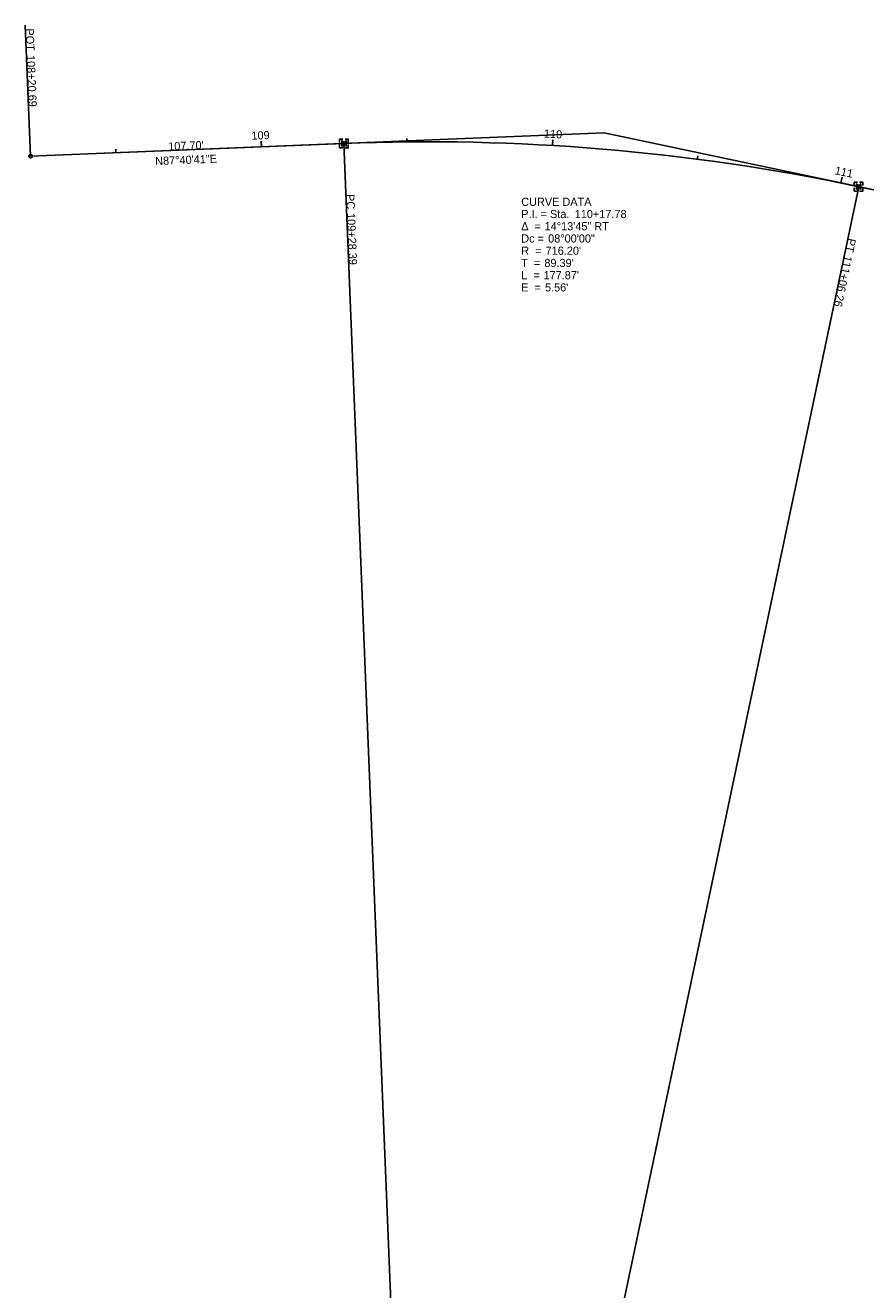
# Model space of a CAD drawing. Extents: x 2003596 to 2006933, y 570827 to 573780.
# Drawn here: x 2003595.8 to 2003884.4, y 572548.4 to 572982.7 of the extents above; entities that cross this region are included whole.
import ezdxf

# ---------------------------------------------------------------- set-up
doc = ezdxf.new("R2010")
doc.units = 0
for name, color, linetype in [('GE_X_Alignment', 7, 'Continuous'), ('GE_X_Alignment_1000_Bearings', 7, 'Continuous'), ('GE_X_Alignment_1000_Cardinal_Points', 7, 'Continuous'), ('GE_X_Alignment_1000_Curve_Data', 7, 'Continuous'), ('GE_X_Alignment_1000_Distances', 7, 'Continuous'), ('GE_X_Alignment_1000_Stations', 7, 'Continuous'), ('GE_X_Alignment_100_Bearings', 7, 'Continuous'), ('GE_X_Alignment_100_Cardinal_Points', 7, 'Continuous'), ('GE_X_Alignment_100_Curve_Data', 7, 'Continuous'), ('GE_X_Alignment_100_Distances', 7, 'Continuous'), ('GE_X_Alignment_100_Stations', 7, 'Continuous'), ('GE_X_Alignment_500_Bearings', 7, 'Continuous'), ('GE_X_Alignment_500_Cardinal_Points', 7, 'Continuous'), ('GE_X_Alignment_500_Curve_Data', 7, 'Continuous'), ('GE_X_Alignment_500_Distances', 7, 'Continuous'), ('GE_X_Alignment_500_Stations', 7, 'Continuous'), ('SC_Scratch1', 7, 'Continuous'), ('SV_X_Mon_Cells_Found', 7, 'Continuous'), ('SV_X_Random_Point', 7, 'Continuous')]:
    doc.layers.add(name, color=color, linetype=linetype)

msp = doc.modelspace()

# ---------------------------------------------------------------- linework, layer by layer
at = {"layer": 'GE_X_Alignment'}
for p, q in [((2003597.61, 572937.73), (2003705.22, 572942.09)), ((2003882.01, 572927.27), (2004086.95, 572884.06))]:
    msp.add_line(p, q, dxfattribs=at)
msp.add_arc((2003734.24, 572226.48), 716.2, 78.09264, 92.32181, dxfattribs=at)
at = {"layer": 'GE_X_Alignment_1000_Cardinal_Points'}
for p, q in [((2003597.61, 572937.73), (2003595.79, 572982.69)), ((2003705.22, 572942.09), (2003707.04, 572897.13)), ((2003882.01, 572927.27), (2003872.72, 572883.24))]:
    msp.add_line(p, q, dxfattribs=at)
for centre in [(2003705.22, 572942.09), (2003597.61, 572937.73), (2003882.01, 572927.27)]:
    msp.add_circle(centre, 0.6, dxfattribs=at)
at = {"layer": 'GE_X_Alignment_1000_Stations'}
msp.add_line((2003776.8, 572941.42), (2003776.92, 572943.41), dxfattribs=at)
at = {"layer": 'GE_X_Alignment_100_Cardinal_Points'}
for p, q in [((2003597.61, 572937.73), (2003595.79, 572982.69)), ((2003705.22, 572942.09), (2003707.04, 572897.13)), ((2003882.01, 572927.27), (2003872.72, 572883.24))]:
    msp.add_line(p, q, dxfattribs=at)
for centre in [(2003705.22, 572942.09), (2003597.61, 572937.73), (2003882.01, 572927.27)]:
    msp.add_circle(centre, 0.6, dxfattribs=at)
at = {"layer": 'GE_X_Alignment_100_Stations'}
for p, q in [((2003676.85, 572940.94), (2003676.77, 572942.94)), ((2003726.82, 572942.64), (2003726.81, 572943.84)), ((2003776.8, 572941.42), (2003776.92, 572943.41)), ((2003626.89, 572938.92), (2003626.85, 572940.12)), ((2003826.56, 572936.71), (2003826.72, 572937.9)), ((2003875.88, 572928.54), (2003876.28, 572930.5))]:
    msp.add_line(p, q, dxfattribs=at)
at = {"layer": 'GE_X_Alignment_500_Cardinal_Points'}
for p, q in [((2003597.61, 572937.73), (2003595.79, 572982.69)), ((2003705.22, 572942.09), (2003707.04, 572897.13)), ((2003882.01, 572927.27), (2003872.72, 572883.24))]:
    msp.add_line(p, q, dxfattribs=at)
for centre in [(2003705.22, 572942.09), (2003597.61, 572937.73), (2003882.01, 572927.27)]:
    msp.add_circle(centre, 0.6, dxfattribs=at)
at = {"layer": 'GE_X_Alignment_500_Stations'}
for p, q in [((2003676.85, 572940.94), (2003676.8, 572942.14)), ((2003776.8, 572941.42), (2003776.92, 572943.41)), ((2003875.88, 572928.54), (2003876.12, 572929.71))]:
    msp.add_line(p, q, dxfattribs=at)
at = {"layer": 'SC_Scratch1'}
for p, q in [((2003597.61, 572937.73), (2003794.54, 572945.72)), ((2003794.54, 572945.72), (2004215.36, 572856.98)), ((2003734.24, 572226.48), (2003705.22, 572942.09)), ((2003734.24, 572226.48), (2003882.01, 572927.27))]:
    msp.add_line(p, q, dxfattribs=at)
at = {"layer": 'SV_X_Mon_Cells_Found'}
for p, q in [((2003705.22, 572942.09), (2003705.22, 572942.09)), ((2003881.94, 572927.28), (2003881.94, 572927.28))]:
    msp.add_line(p, q, dxfattribs=at)
for points in [[(2003703.72, 572942.47), (2003703.72, 572943.6), (2003704.84, 572943.6)], [(2003704.84, 572940.59), (2003703.72, 572940.59), (2003703.72, 572941.72)], [(2003704.48, 572941.09), (2003704.48, 572943.09), (2003705.22, 572941.09), (2003705.96, 572943.09), (2003705.96, 572941.09)], [(2003705.58, 572943.6), (2003706.72, 572943.6), (2003706.72, 572942.47)], [(2003706.72, 572941.72), (2003706.72, 572940.59), (2003705.58, 572940.59)], [(2003880.44, 572927.66), (2003880.44, 572928.78), (2003881.56, 572928.78)], [(2003881.2, 572926.28), (2003881.2, 572928.28), (2003881.94, 572926.28), (2003882.68, 572928.28), (2003882.68, 572926.28)], [(2003882.3, 572928.78), (2003883.44, 572928.78), (2003883.44, 572927.66)], [(2003881.56, 572925.78), (2003880.44, 572925.78), (2003880.44, 572926.9)], [(2003883.44, 572926.9), (2003883.44, 572925.78), (2003882.3, 572925.78)]]:
    msp.add_lwpolyline(points, dxfattribs=at)
at = {"layer": 'SV_X_Random_Point'}
for p, q in [((2003881.34, 572926.6), (2003882.68, 572927.94)), ((2003881.34, 572927.94), (2003882.68, 572926.6))]:
    msp.add_line(p, q, dxfattribs=at)

# ---------------------------------------------------------------- texts
at = {"layer": 'GE_X_Alignment_1000_Bearings'}
msp.add_text('N87°40\'41"E', height=2.8, rotation=2.3218, dxfattribs=at).set_placement((2003640.44, 572934.66))
at = {"layer": 'GE_X_Alignment_1000_Cardinal_Points'}
for s, rotation, p in [('POT', 272.3218, (2003595.88, 572981.55)), ('108+20.69', 272.3218, (2003596.25, 572972.43)), ('PC', 272.3218, (2003705.97, 572924.66)), ('109+28.39', 272.3218, (2003706.24, 572918.14)), ('PT', 258.0925, (2003878.36, 572909.72)), ('111+06.26', 258.0925, (2003877.1, 572903.76))]:
    msp.add_text(s, height=2.8, rotation=rotation, dxfattribs=at).set_placement(p)
at = {"layer": 'GE_X_Alignment_1000_Curve_Data'}
for s, p in [('CURVE DATA', (2003766.1, 572920.68)), ('P.I. = Sta. ', (2003766.1, 572916.48)), ('110+17.78', (2003784.47, 572916.48)), ('Δ  = ', (2003766.1, 572912.28)), ('14°13\'45" RT', (2003774.13, 572912.28)), ('08°00\'00"', (2003775.34, 572908.08)), ('Dc = ', (2003766.1, 572908.08)), ('R  = ', (2003766.1, 572903.88)), ("716.20'", (2003774.47, 572903.88)), ('T  = ', (2003766.1, 572899.68)), ("89.39'", (2003774.04, 572899.68)), ('L  = ', (2003766.1, 572895.48)), ("177.87'", (2003773.75, 572895.48)), ('E  = ', (2003766.1, 572891.28)), ("5.56'", (2003774.26, 572891.28))]:
    msp.add_text(s, height=2.8, dxfattribs=at).set_placement(p)
at = {"layer": 'GE_X_Alignment_1000_Distances'}
msp.add_text("107.70'", height=2.8, rotation=2.3218, dxfattribs=at).set_placement((2003644.93, 572939.7))
at = {"layer": 'GE_X_Alignment_1000_Stations'}
msp.add_text('110', height=2.8, rotation=356.593, dxfattribs=at).set_placement((2003773.82, 572944.15))
at = {"layer": 'GE_X_Alignment_100_Bearings'}
msp.add_text('N87°40\'41"E', height=2.8, rotation=2.3218, dxfattribs=at).set_placement((2003640.44, 572934.66))
at = {"layer": 'GE_X_Alignment_100_Cardinal_Points'}
for s, rotation, p in [('POT', 272.3218, (2003595.88, 572981.55)), ('108+20.69', 272.3218, (2003596.25, 572972.43)), ('PC', 272.3218, (2003705.97, 572924.66)), ('109+28.39', 272.3218, (2003706.24, 572918.14)), ('PT', 258.0925, (2003878.36, 572909.72)), ('111+06.26', 258.0925, (2003877.1, 572903.76))]:
    msp.add_text(s, height=2.8, rotation=rotation, dxfattribs=at).set_placement(p)
at = {"layer": 'GE_X_Alignment_100_Curve_Data'}
for s, p in [('CURVE DATA', (2003766.1, 572920.68)), ('P.I. = Sta. ', (2003766.1, 572916.48)), ('110+17.78', (2003784.47, 572916.48)), ('Δ  = ', (2003766.1, 572912.28)), ('14°13\'45" RT', (2003774.13, 572912.28)), ('08°00\'00"', (2003775.34, 572908.08)), ('Dc = ', (2003766.1, 572908.08)), ('R  = ', (2003766.1, 572903.88)), ("716.20'", (2003774.47, 572903.88)), ('T  = ', (2003766.1, 572899.68)), ("89.39'", (2003774.04, 572899.68)), ('L  = ', (2003766.1, 572895.48)), ("177.87'", (2003773.75, 572895.48)), ('E  = ', (2003766.1, 572891.28)), ("5.56'", (2003774.26, 572891.28))]:
    msp.add_text(s, height=2.8, dxfattribs=at).set_placement(p)
at = {"layer": 'GE_X_Alignment_100_Distances'}
msp.add_text("107.70'", height=2.8, rotation=2.3218, dxfattribs=at).set_placement((2003644.93, 572939.7))
at = {"layer": 'GE_X_Alignment_100_Stations'}
for s, rotation, p in [('109', 2.3218, (2003673.5, 572943.36)), ('110', 356.593, (2003773.82, 572944.15)), ('111', 348.5931, (2003873.61, 572931.54))]:
    msp.add_text(s, height=2.8, rotation=rotation, dxfattribs=at).set_placement(p)
at = {"layer": 'GE_X_Alignment_500_Bearings'}
msp.add_text('N87°40\'41"E', height=2.8, rotation=2.3218, dxfattribs=at).set_placement((2003640.44, 572934.66))
at = {"layer": 'GE_X_Alignment_500_Cardinal_Points'}
for s, rotation, p in [('POT', 272.3218, (2003595.88, 572981.55)), ('108+20.69', 272.3218, (2003596.25, 572972.43)), ('PC', 272.3218, (2003705.97, 572924.66)), ('109+28.39', 272.3218, (2003706.24, 572918.14)), ('PT', 258.0925, (2003878.36, 572909.72)), ('111+06.26', 258.0925, (2003877.1, 572903.76))]:
    msp.add_text(s, height=2.8, rotation=rotation, dxfattribs=at).set_placement(p)
at = {"layer": 'GE_X_Alignment_500_Curve_Data'}
for s, p in [('CURVE DATA', (2003766.1, 572920.68)), ('P.I. = Sta. ', (2003766.1, 572916.48)), ('110+17.78', (2003784.47, 572916.48)), ('Δ  = ', (2003766.1, 572912.28)), ('14°13\'45" RT', (2003774.13, 572912.28)), ('08°00\'00"', (2003775.34, 572908.08)), ('Dc = ', (2003766.1, 572908.08)), ('R  = ', (2003766.1, 572903.88)), ("716.20'", (2003774.47, 572903.88)), ('T  = ', (2003766.1, 572899.68)), ("89.39'", (2003774.04, 572899.68)), ('L  = ', (2003766.1, 572895.48)), ("177.87'", (2003773.75, 572895.48)), ('E  = ', (2003766.1, 572891.28)), ("5.56'", (2003774.26, 572891.28))]:
    msp.add_text(s, height=2.8, dxfattribs=at).set_placement(p)
at = {"layer": 'GE_X_Alignment_500_Distances'}
msp.add_text("107.70'", height=2.8, rotation=2.3218, dxfattribs=at).set_placement((2003644.93, 572939.7))
at = {"layer": 'GE_X_Alignment_500_Stations'}
msp.add_text('110', height=2.8, rotation=356.593, dxfattribs=at).set_placement((2003773.82, 572944.15))

doc.saveas('drawing.dxf')
